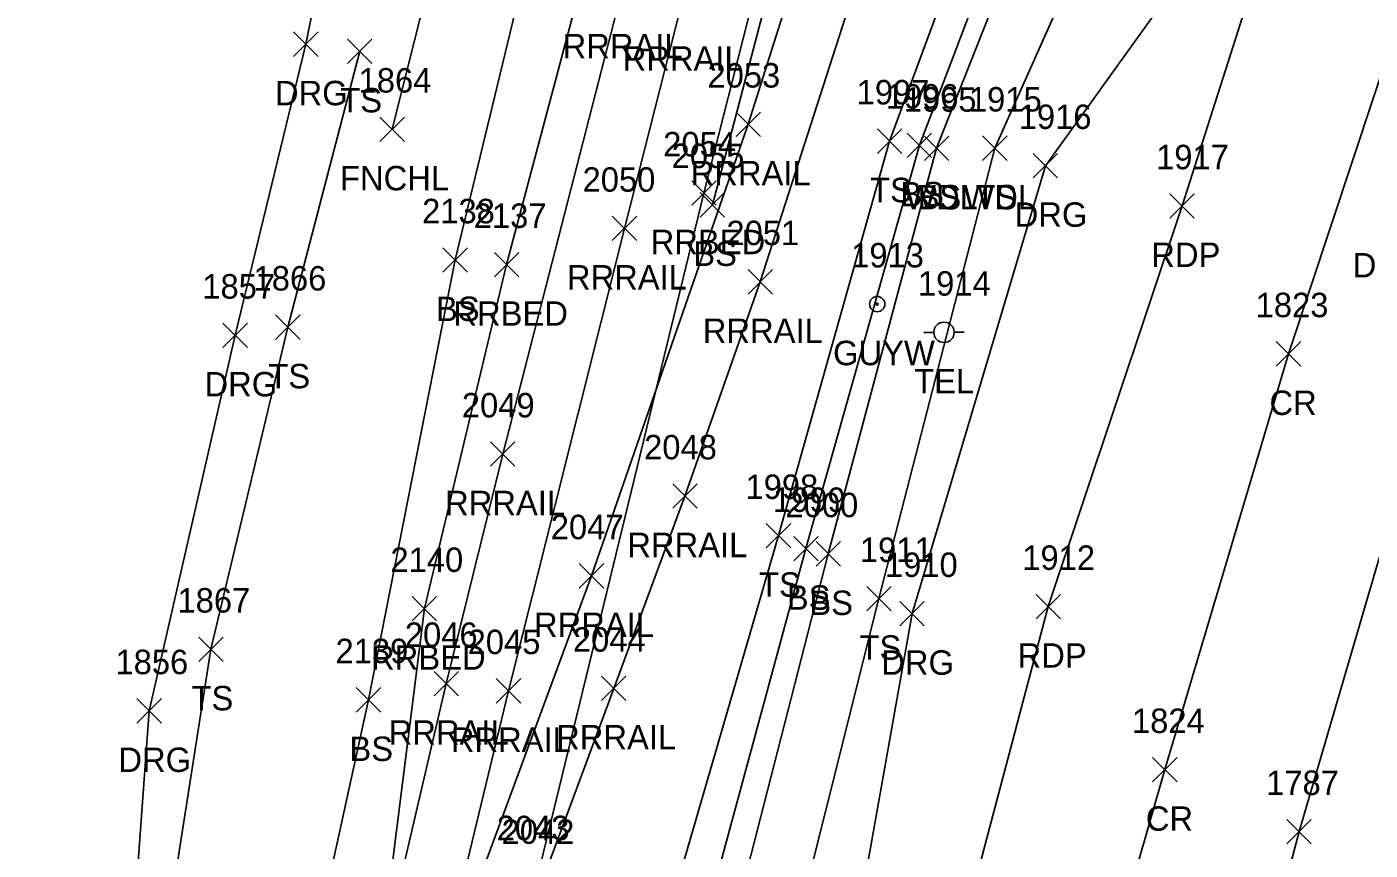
# Model space of a CAD drawing. Extents: x 1769141 to 1770817, y 735471 to 742405.
# Drawn here: x 1770199.1 to 1770309, y 742041.1 to 742108.4 of the extents above; entities that cross this region are included whole.
import ezdxf

# ---------------------------------------------------------------- set-up
doc = ezdxf.new("R2010")
doc.units = 0
for name, color, linetype in [('L_A', 7, 'Continuous'), ('L_I', 7, 'Continuous'), ('L_TIC', 7, 'Continuous'), ('LAWA', 7, 'Continuous'), ('LELB', 7, 'Continuous'), ('LFNC', 7, 'Continuous'), ('P_A', 7, 'Continuous'), ('P_I', 7, 'Continuous'), ('P_TIC', 7, 'Continuous'), ('PET', 7, 'Continuous'), ('PRC', 7, 'Continuous'), ('R_A', 7, 'Continuous'), ('R_I', 7, 'Continuous'), ('R_TIC', 7, 'Continuous'), ('RDG', 7, 'Continuous'), ('RR', 7, 'Continuous'), ('RRB', 7, 'Continuous'), ('U_A', 7, 'Continuous'), ('U_I', 7, 'Continuous'), ('UP', 7, 'Continuous'), ('UPGW', 7, 'Continuous')]:
    doc.layers.add(name, color=color, linetype=linetype)

msp = doc.modelspace()

# ---------------------------------------------------------------- linework, layer by layer
at = {"layer": 'L_TIC'}
for points in [[(1770225.34, 742105.44), (1770227.34, 742107.44)], [(1770227.34, 742105.44), (1770225.34, 742107.44)], [(1770227.99, 742099.06), (1770229.99, 742101.06)], [(1770229.99, 742099.06), (1770227.99, 742101.06)], [(1770268.66, 742098.09), (1770270.66, 742100.09)], [(1770270.66, 742098.09), (1770268.66, 742100.09)], [(1770271.1, 742097.75), (1770273.1, 742099.75)], [(1770273.1, 742097.75), (1770271.1, 742099.75)], [(1770272.51, 742097.5), (1770274.51, 742099.5)], [(1770274.51, 742097.5), (1770272.51, 742099.5)], [(1770272.51, 742097.5), (1770274.51, 742099.5)], [(1770274.51, 742097.5), (1770272.51, 742099.5)], [(1770277.27, 742097.51), (1770279.27, 742099.51)], [(1770279.27, 742097.51), (1770277.27, 742099.51)], [(1770277.27, 742097.51), (1770279.27, 742099.51)], [(1770279.27, 742097.51), (1770277.27, 742099.51)], [(1770254.17, 742092.88), (1770256.17, 742094.88)], [(1770256.17, 742092.88), (1770254.17, 742094.88)], [(1770233.14, 742088.37), (1770235.14, 742090.37)], [(1770235.14, 742088.37), (1770233.14, 742090.37)], [(1770219.46, 742082.87), (1770221.46, 742084.87)], [(1770221.46, 742082.87), (1770219.46, 742084.87)], [(1770259.58, 742065.82), (1770261.58, 742067.82)], [(1770261.58, 742065.82), (1770259.58, 742067.82)], [(1770261.82, 742064.76), (1770263.82, 742066.76)], [(1770263.82, 742064.76), (1770261.82, 742066.76)], [(1770263.65, 742064.33), (1770265.65, 742066.33)], [(1770265.65, 742064.33), (1770263.65, 742066.33)], [(1770267.79, 742060.67), (1770269.79, 742062.67)], [(1770269.79, 742060.67), (1770267.79, 742062.67)], [(1770213.18, 742056.53), (1770215.18, 742058.53)], [(1770215.18, 742056.53), (1770213.18, 742058.53)], [(1770226.06, 742052.39), (1770228.06, 742054.39)], [(1770228.06, 742052.39), (1770226.06, 742054.39)]]:
    msp.add_lwpolyline(points, dxfattribs=at)
at = {"layer": 'LAWA'}
msp.add_lwpolyline([(1770278.27, 742098.51), (1770292.63, 742130.75), (1770300.5, 742163.1), (1770310.78, 742196.92), (1770318.92, 742223), (1770331.76, 742252.5), (1770324.85, 742244.64), (1770302.11, 742188.56), (1770291.13, 742150.41), (1770288.91, 742136.29), (1770280.1, 742115.2), (1770273.51, 742098.5)], dxfattribs=at)
at = {"layer": 'LELB'}
for points in [[(1770332.23, 742396.99), (1770317.41, 742358.29), (1770305.3, 742323.67), (1770290.81, 742279.34), (1770278.82, 742239.77), (1770261.32, 742196.43), (1770254.37, 742156.7), (1770242.09, 742122.31), (1770234.14, 742089.37), (1770227.06, 742053.39), (1770219.68, 742019.63), (1770213.36, 741989.97), (1770210.16, 741976.3), (1770206.14, 741961.98)], [(1770380.12, 742366.91), (1770363.06, 742334.87), (1770342.94, 742294.53), (1770326.94, 742263.13), (1770309.84, 742221.71), (1770298.92, 742189.88), (1770289.69, 742167.82), (1770287.13, 742167.67), (1770285.1, 742161.65), (1770288.13, 742159.66), (1770284.67, 742135.52), (1770276.3, 742117.05), (1770269.66, 742099.09), (1770260.58, 742066.82), (1770250.33, 742031.54), (1770242.02, 742000.43), (1770236.09, 741978.68), (1770232.48, 741959.64)], [(1770381.35, 742366.29), (1770364.19, 742334.21), (1770345.62, 742293.81), (1770328.91, 742260.94), (1770312.07, 742221.07), (1770300.68, 742188.95), (1770290.98, 742164.79), (1770288.07, 742165.78), (1770286.6, 742162.38), (1770289.46, 742160.5), (1770286.3, 742134.62), (1770278.73, 742116.17), (1770272.1, 742098.75), (1770262.82, 742065.76), (1770253.59, 742031.78), (1770244.44, 742003.2), (1770237.54, 741978.15), (1770232.48, 741959.64)], [(1770255.17, 742093.88), (1770277.55, 742179.23), (1770295.2, 742239), (1770314.05, 742295.07)], [(1770226.34, 742106.44), (1770220.46, 742083.87), (1770214.18, 742057.53), (1770210.02, 742031.04), (1770208.67, 742009.82), (1770201.53, 741974.96), (1770199.13, 741957.5), (1770202.93, 741951.2)], [(1770273.51, 742098.5), (1770264.65, 742065.33), (1770255.84, 742030.99), (1770246.23, 741999.52), (1770240.59, 741977.35), (1770237.21, 741958.89), (1770236.39, 741949.58), (1770227.75, 741950.19), (1770220.56, 741953.97), (1770219.87, 741959.41)], [(1770238.83, 741941.3), (1770241.44, 741950.47), (1770243.39, 741955.56), (1770247.43, 741975.41), (1770250.9, 741993.87), (1770260.08, 742026.94), (1770268.79, 742061.67), (1770278.27, 742098.51)]]:
    msp.add_lwpolyline(points, dxfattribs=at)
at = {"layer": 'LFNC'}
msp.add_lwpolyline([(1770243.85, 742161.51), (1770237.24, 742132.9), (1770228.99, 742100.06)], dxfattribs=at)
at = {"layer": 'P_TIC'}
for points in [[(1770292.57, 742092.79), (1770294.57, 742094.79)], [(1770294.57, 742092.79), (1770292.57, 742094.79)], [(1770301.28, 742080.69), (1770303.28, 742082.69)], [(1770303.28, 742080.69), (1770301.28, 742082.69)], [(1770281.64, 742060.02), (1770283.64, 742062.02)], [(1770283.64, 742060.02), (1770281.64, 742062.02)], [(1770291.17, 742046.68), (1770293.17, 742048.68)], [(1770293.17, 742046.68), (1770291.17, 742048.68)], [(1770302.14, 742041.61), (1770304.14, 742043.61)], [(1770304.14, 742041.61), (1770302.14, 742043.61)]]:
    msp.add_lwpolyline(points, dxfattribs=at)
at = {"layer": 'PET'}
for points in [[(1770272.7, 742023.54), (1770282.64, 742061.02), (1770293.57, 742093.79), (1770304.4, 742127.71), (1770313.88, 742157.38), (1770333.72, 742213.99), (1770354.85, 742269.34), (1770368.55, 742301.73), (1770378.75, 742329.81), (1770392.05, 742361.37)], [(1770296.04, 742015.55), (1770303.14, 742042.61), (1770312.37, 742074.12), (1770317.15, 742087.84), (1770319.53, 742093.81), (1770328.4, 742119.72), (1770345.72, 742170.91), (1770359.21, 742210.32), (1770377.16, 742259.11), (1770392.46, 742300.59)]]:
    msp.add_lwpolyline(points, dxfattribs=at)
at = {"layer": 'PRC'}
msp.add_lwpolyline([(1770386.13, 742315.42), (1770368.53, 742271.05), (1770352, 742227.48), (1770338.73, 742191.59), (1770324.94, 742150.68), (1770312.78, 742113.37), (1770302.28, 742081.69), (1770292.17, 742047.68), (1770283.01, 742015.74), (1770275.68, 741981.9), (1770269.49, 741954.54), (1770264.41, 741931.75), (1770261.81, 741920.34)], dxfattribs=at)
at = {"layer": 'R_TIC'}
for points in [[(1770220.93, 742106.02), (1770222.93, 742108.02)], [(1770222.93, 742106.02), (1770220.93, 742108.02)], [(1770257.11, 742099.47), (1770259.11, 742101.47)], [(1770259.11, 742099.47), (1770257.11, 742101.47)], [(1770281.4, 742096.08), (1770283.4, 742098.08)], [(1770283.4, 742096.08), (1770281.4, 742098.08)], [(1770253.48, 742093.84), (1770255.48, 742095.84)], [(1770255.48, 742093.84), (1770253.48, 742095.84)], [(1770246.99, 742090.95), (1770248.99, 742092.95)], [(1770248.99, 742090.95), (1770246.99, 742092.95)], [(1770237.35, 742087.99), (1770239.35, 742089.99)], [(1770239.35, 742087.99), (1770237.35, 742089.99)], [(1770258.09, 742086.58), (1770260.09, 742088.58)], [(1770260.09, 742086.58), (1770258.09, 742088.58)], [(1770215.16, 742082.21), (1770217.16, 742084.21)], [(1770217.16, 742082.21), (1770215.16, 742084.21)], [(1770237.03, 742072.49), (1770239.03, 742074.49)], [(1770239.03, 742072.49), (1770237.03, 742074.49)], [(1770251.93, 742069.06), (1770253.93, 742071.06)], [(1770253.93, 742069.06), (1770251.93, 742071.06)], [(1770244.29, 742062.53), (1770246.29, 742064.53)], [(1770246.29, 742062.53), (1770244.29, 742064.53)], [(1770230.63, 742059.85), (1770232.63, 742061.85)], [(1770232.63, 742059.85), (1770230.63, 742061.85)], [(1770270.5, 742059.44), (1770272.5, 742061.44)], [(1770272.5, 742059.44), (1770270.5, 742061.44)], [(1770232.42, 742053.72), (1770234.42, 742055.72)], [(1770234.42, 742053.72), (1770232.42, 742055.72)], [(1770237.5, 742053.13), (1770239.5, 742055.13)], [(1770239.5, 742053.13), (1770237.5, 742055.13)], [(1770246.11, 742053.33), (1770248.11, 742055.33)], [(1770248.11, 742053.33), (1770246.11, 742055.33)], [(1770208.12, 742051.49), (1770210.12, 742053.49)], [(1770210.12, 742051.49), (1770208.12, 742053.49)]]:
    msp.add_lwpolyline(points, dxfattribs=at)
at = {"layer": 'RDG'}
for points in [[(1770207.76, 742033.79), (1770209.12, 742052.49), (1770216.16, 742083.21), (1770221.93, 742107.02), (1770228.05, 742137.22), (1770216.02, 742141.81)], [(1770264.42, 741997.74), (1770265.66, 742027.49), (1770271.5, 742060.44), (1770282.4, 742097.08), (1770304.4, 742127.71)]]:
    msp.add_lwpolyline(points, dxfattribs=at)
at = {"layer": 'RR'}
for points in [[(1770228.86, 742035.21), (1770233.42, 742054.72), (1770238.03, 742073.49), (1770247.64, 742110.86), (1770257.95, 742148.59), (1770267.65, 742182.8), (1770278.27, 742218.42), (1770281.99, 742230.6), (1770291.93, 742261.78), (1770298.46, 742281.94), (1770310.78, 742317.95), (1770323.27, 742353.88), (1770336.53, 742389.56)], [(1770234.04, 742035.58), (1770238.5, 742054.13), (1770247.99, 742091.95), (1770252.55, 742109.85), (1770260.28, 742138.64), (1770270.31, 742174.37), (1770278.8, 742203.12), (1770290.02, 742239.43), (1770296.47, 742259.99), (1770308.47, 742295.99), (1770320.74, 742331.91), (1770333.76, 742367.71)], [(1770212.41, 741956.11), (1770215.59, 741972.32), (1770224.21, 742004.12), (1770229.48, 742020.05), (1770231.83, 742026.33), (1770233.36, 742030.93), (1770234.9, 742035.43), (1770245.29, 742063.53), (1770258.11, 742100.47), (1770265.99, 742125.45), (1770269.66, 742137.91), (1770278.76, 742169.79), (1770287.08, 742199.09), (1770296.7, 742230.77), (1770306.54, 742262.18), (1770316.86, 742293.7)], [(1770216.86, 741956.06), (1770220.47, 741971.24), (1770224.73, 741988.15), (1770230.52, 742007.6), (1770241.28, 742038.61), (1770247.11, 742054.33), (1770252.93, 742070.06), (1770259.09, 742087.58), (1770269.15, 742118.93), (1770274.55, 742137.03), (1770276.73, 742144.46), (1770280.27, 742157.18), (1770289.26, 742188.86), (1770295.02, 742208.42), (1770297.09, 742215.37), (1770298.78, 742220.71), (1770308.51, 742252.21), (1770318.64, 742283.66)]]:
    msp.add_lwpolyline(points, dxfattribs=at)
at = {"layer": 'RRB'}
for points in [[(1770334.91, 742396.24), (1770320.98, 742356.43), (1770309.38, 742323.07), (1770294.31, 742278.11), (1770281.7, 742240.39), (1770267.62, 742193.22), (1770256.86, 742155.94), (1770246.81, 742120.87), (1770238.35, 742088.99), (1770231.63, 742060.85), (1770227.63, 742029.05), (1770215.73, 741989.64), (1770208.91, 741960.54)], [(1770219.87, 741959.41), (1770227.39, 741986.94), (1770232.28, 742006.89), (1770240.88, 742038.91), (1770254.48, 742094.84), (1770276.07, 742179.76), (1770293.54, 742239.51), (1770311.55, 742295.01)]]:
    msp.add_lwpolyline(points, dxfattribs=at)
at = {"layer": 'UP'}
for p, q in [((1770272.45, 742083.44), (1770273.27, 742083.44)), ((1770274.11, 742083.45), (1770274.11, 742083.45)), ((1770275.77, 742083.45), (1770274.94, 742083.45)), ((1770274.94, 742083.45), (1770274.94, 742083.45)), ((1770275.77, 742083.45), (1770275.77, 742083.45))]:
    msp.add_line(p, q, dxfattribs=at)
msp.add_circle((1770274.11, 742083.45), 0.833, dxfattribs=at)
at = {"layer": 'UPGW'}
for radius in [0.625, 0.0833]:
    msp.add_circle((1770268.65, 742085.76), radius, dxfattribs=at)

# ---------------------------------------------------------------- texts
at = {"layer": 'L_A'}
for s, p in [('TS', (1770224.75, 742101.44)), ('FNCHL', (1770224.73, 742095.06)), ('TS', (1770268.07, 742094.09)), ('BS', (1770270.54, 742093.75)), ('WDL', (1770270.93, 742093.5)), ('BS', (1770271.95, 742093.5)), ('WDL', (1770275.69, 742093.51)), ('TS', (1770276.68, 742093.51)), ('BS', (1770253.61, 742088.88)), ('BS', (1770232.58, 742084.37)), ('TS', (1770218.87, 742078.87)), ('TS', (1770258.99, 742061.82)), ('BS', (1770261.26, 742060.76)), ('BS', (1770263.1, 742060.33)), ('TS', (1770267.2, 742056.67)), ('TS', (1770212.59, 742052.53)), ('BS', (1770225.5, 742048.39))]:
    msp.add_text(s, height=2, dxfattribs=at).set_placement(p)
at = {"layer": 'L_I'}
for s, p in [('1864', (1770226.25, 742103.06)), ('1997', (1770266.97, 742102.09)), ('1996', (1770269.35, 742101.75)), ('1995', (1770270.82, 742101.5)), ('1995', (1770270.82, 742101.5)), ('1915', (1770276.15, 742101.51)), ('1915', (1770276.15, 742101.51)), ('2055', (1770251.84, 742096.88)), ('2138', (1770231.44, 742092.37)), ('1866', (1770217.66, 742086.87)), ('1998', (1770257.88, 742069.82)), ('1999', (1770260.12, 742068.76)), ('2000', (1770261.15, 742068.33)), ('1911', (1770267.23, 742064.67)), ('1867', (1770211.44, 742060.53)), ('2139', (1770224.36, 742056.39))]:
    msp.add_text(s, height=2, dxfattribs=at).set_placement(p)
at = {"layer": 'P_A'}
for s, p in [('RDP', (1770291.06, 742088.79)), ('CR', (1770300.72, 742076.69)), ('RDP', (1770280.13, 742056.02)), ('CR', (1770290.61, 742042.68))]:
    msp.add_text(s, height=2, dxfattribs=at).set_placement(p)
at = {"layer": 'P_I'}
for s, p in [('1917', (1770291.45, 742096.79)), ('1823', (1770299.59, 742084.69)), ('1912', (1770280.51, 742064.02)), ('1824', (1770289.48, 742050.68)), ('1787', (1770300.45, 742045.61))]:
    msp.add_text(s, height=2, dxfattribs=at).set_placement(p)
at = {"layer": 'R_A'}
for s, p in [('RRRAIL', (1770242.93, 742105.86)), ('RRRAIL', (1770247.84, 742104.85)), ('DRG', (1770219.41, 742102.02)), ('RRRAIL', (1770253.4, 742095.47)), ('DRG', (1770279.89, 742092.08)), ('RRBED', (1770250.13, 742089.84)), ('DRP CP SWC ST', (1770307.53, 742087.94)), ('RRRAIL', (1770243.28, 742086.95)), ('RRBED', (1770234, 742083.99)), ('RRRAIL', (1770254.39, 742082.58)), ('DRG', (1770213.65, 742078.21)), ('RRRAIL', (1770233.32, 742068.49)), ('RRRAIL', (1770248.22, 742065.06)), ('RRRAIL', (1770240.59, 742058.53)), ('RRBED', (1770227.27, 742055.85)), ('DRG', (1770268.98, 742055.44)), ('RRRAIL', (1770228.71, 742049.72)), ('RRRAIL', (1770242.4, 742049.33)), ('RRRAIL', (1770233.79, 742049.13)), ('DRG', (1770206.61, 742047.49))]:
    msp.add_text(s, height=2, dxfattribs=at).set_placement(p)
at = {"layer": 'R_I'}
for s, p in [('2053', (1770254.77, 742103.47)), ('1916', (1770280.22, 742100.08)), ('2054', (1770251.15, 742097.84)), ('2050', (1770244.56, 742094.95)), ('2137', (1770235.66, 742091.99)), ('2051', (1770256.32, 742090.58)), ('1857', (1770213.47, 742086.21)), ('2049', (1770234.69, 742076.49)), ('2048', (1770249.59, 742073.06)), ('2047', (1770241.96, 742066.53)), ('2140', (1770228.85, 742063.85)), ('1910', (1770269.28, 742063.44)), ('2046', (1770230.03, 742057.72)), ('2045', (1770235.16, 742057.13)), ('2044', (1770243.77, 742057.33)), ('1856', (1770206.37, 742055.49)), ('2043', (1770237.54, 742041.91)), ('2042', (1770237.94, 742041.61))]:
    msp.add_text(s, height=2, dxfattribs=at).set_placement(p)
at = {"layer": 'U_A'}
for s, p in [('GUYW', (1770265.04, 742080.76)), ('TEL', (1770271.67, 742078.45))]:
    msp.add_text(s, height=2, dxfattribs=at).set_placement(p)
at = {"layer": 'U_I'}
for s, p in [('1913', (1770266.52, 742088.76)), ('1914', (1770271.98, 742086.45))]:
    msp.add_text(s, height=2, dxfattribs=at).set_placement(p)

doc.saveas('drawing.dxf')
